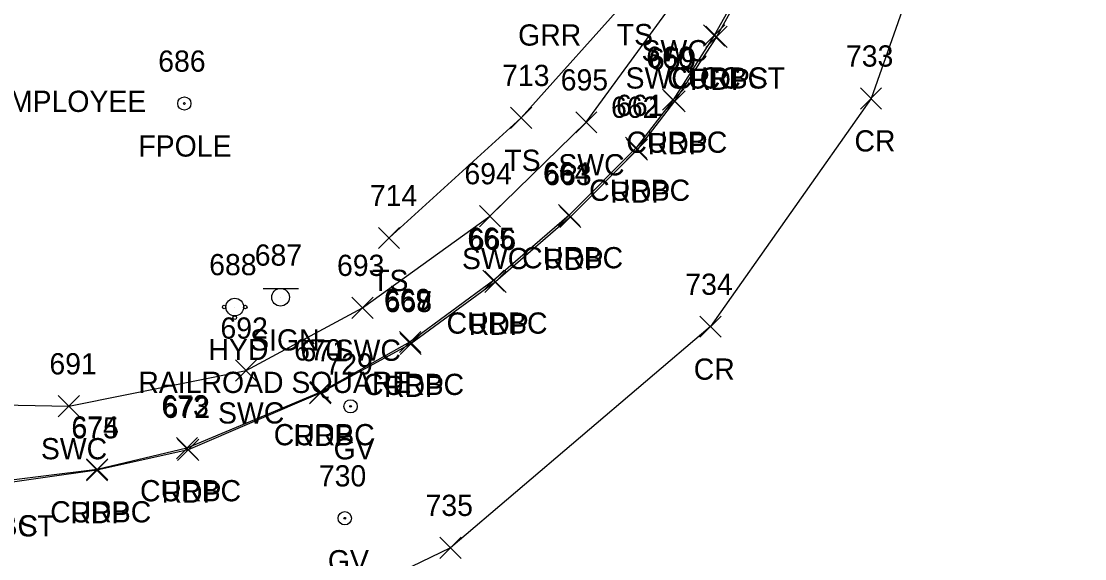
# Model space of a CAD drawing. Extents: x 1715662 to 1717487, y 887396 to 890004.
# Drawn here: x 1716519.9 to 1716620, y 888252.4 to 888303 of the extents above; entities that cross this region are included whole.
import ezdxf

# ---------------------------------------------------------------- set-up
doc = ezdxf.new("R2010")
doc.units = 0
for name, color, linetype in [('L_A', 7, 'Continuous'), ('L_I', 7, 'Continuous'), ('L_TIC', 7, 'Continuous'), ('LELB', 7, 'Continuous'), ('LFP', 7, 'Continuous'), ('P_A', 7, 'Continuous'), ('P_I', 7, 'Continuous'), ('P_TIC', 7, 'Continuous'), ('PET', 7, 'Continuous'), ('PRC', 7, 'Continuous'), ('R_A', 7, 'Continuous'), ('R_I', 7, 'Continuous'), ('R_TIC', 7, 'Continuous'), ('RC', 7, 'Continuous'), ('RSW', 7, 'Continuous'), ('S_A', 7, 'Continuous'), ('S_C', 7, 'Continuous'), ('S_I', 7, 'Continuous'), ('SSGN', 7, 'Continuous'), ('U_A', 7, 'Continuous'), ('U_I', 7, 'Continuous'), ('UWFH', 7, 'Continuous'), ('UWV', 7, 'Continuous')]:
    doc.layers.add(name, color=color, linetype=linetype)

msp = doc.modelspace()

# ---------------------------------------------------------------- linework, layer by layer
at = {"layer": 'L_TIC'}
for points in [[(1716565.96, 888292.94), (1716567.96, 888294.94)], [(1716567.96, 888292.94), (1716565.96, 888294.94)], [(1716553.51, 888281.62), (1716555.51, 888283.62)], [(1716555.51, 888281.62), (1716553.51, 888283.62)]]:
    msp.add_lwpolyline(points, dxfattribs=at)
at = {"layer": 'LELB'}
msp.add_lwpolyline([(1716582.79, 888318.54), (1716577.55, 888305.79), (1716566.96, 888293.94), (1716554.51, 888282.62)], dxfattribs=at)
at = {"layer": 'LFP'}
for radius in [0.625, 0.0833]:
    msp.add_circle((1716535.23, 888295.29), radius, dxfattribs=at)
at = {"layer": 'P_TIC'}
for points in [[(1716584.36, 888300.58), (1716586.36, 888302.58)], [(1716586.36, 888300.58), (1716584.36, 888302.58)], [(1716580.39, 888294.5), (1716582.39, 888296.5)], [(1716582.39, 888294.5), (1716580.39, 888296.5)], [(1716598.91, 888294.77), (1716600.91, 888296.77)], [(1716600.91, 888294.77), (1716598.91, 888296.77)], [(1716576.87, 888289.94), (1716578.87, 888291.94)], [(1716578.87, 888289.94), (1716576.87, 888291.94)], [(1716570.59, 888283.6), (1716572.59, 888285.6)], [(1716572.59, 888283.6), (1716570.59, 888285.6)], [(1716563.54, 888277.49), (1716565.54, 888279.49)], [(1716565.54, 888277.49), (1716563.54, 888279.49)], [(1716583.78, 888273.26), (1716585.78, 888275.26)], [(1716585.78, 888273.26), (1716583.78, 888275.26)], [(1716555.55, 888271.64), (1716557.55, 888273.64)], [(1716557.55, 888271.64), (1716555.55, 888273.64)], [(1716555.55, 888271.63), (1716557.55, 888273.63)], [(1716557.55, 888271.63), (1716555.55, 888273.63)], [(1716547.02, 888267), (1716549.02, 888269)], [(1716549.02, 888267), (1716547.02, 888269)], [(1716534.59, 888261.66), (1716536.59, 888263.66)], [(1716536.59, 888261.66), (1716534.59, 888263.66)], [(1716526, 888259.73), (1716528, 888261.73)], [(1716528, 888259.73), (1716526, 888261.73)], [(1716559.31, 888252.42), (1716561.31, 888254.42)], [(1716561.31, 888252.42), (1716559.31, 888254.42)]]:
    msp.add_lwpolyline(points, dxfattribs=at)
at = {"layer": 'PET'}
msp.add_lwpolyline([(1716628.39, 888359.45), (1716612.85, 888359.68), (1716598.29, 888359.77), (1716597.92, 888344.73), (1716597.23, 888336.42), (1716596.07, 888329.81), (1716593.67, 888319.98), (1716591.95, 888314.93), (1716590.61, 888311.07), (1716585.36, 888301.58), (1716581.39, 888295.5), (1716577.87, 888290.94), (1716571.59, 888284.6), (1716564.54, 888278.49), (1716556.55, 888272.63), (1716556.55, 888272.64), (1716548.02, 888268), (1716535.59, 888262.66), (1716527, 888260.73), (1716516.57, 888259.25)], dxfattribs=at)
at = {"layer": 'PRC'}
msp.add_lwpolyline([(1716612.85, 888359.68), (1716612.17, 888345.49), (1716610.23, 888325.05), (1716599.91, 888295.77), (1716584.78, 888274.26), (1716560.31, 888253.42), (1716535.28, 888241.32), (1716471.98, 888238.42), (1716446.91, 888240.45), (1716423.44, 888242.23), (1716395.99, 888243.46), (1716360.07, 888243.38), (1716329.01, 888242.88), (1716285.79, 888240.52), (1716253.17, 888237.3), (1716220.47, 888232.04), (1716184.13, 888222.3), (1716155.75, 888211.83), (1716125.79, 888199.82), (1716096.66, 888186.57)], dxfattribs=at)
at = {"layer": 'R_TIC'}
for points in [[(1716584.13, 888300.7), (1716586.13, 888302.7)], [(1716586.13, 888300.7), (1716584.13, 888302.7)], [(1716584.13, 888300.7), (1716586.13, 888302.7)], [(1716586.13, 888300.7), (1716584.13, 888302.7)], [(1716580.28, 888294.65), (1716582.28, 888296.65)], [(1716582.28, 888294.65), (1716580.28, 888296.65)], [(1716572.09, 888292.52), (1716574.09, 888294.52)], [(1716574.09, 888292.52), (1716572.09, 888294.52)], [(1716576.78, 888290.12), (1716578.78, 888292.12)], [(1716578.78, 888290.12), (1716576.78, 888292.12)], [(1716563.02, 888283.68), (1716565.02, 888285.68)], [(1716565.02, 888283.68), (1716563.02, 888285.68)], [(1716570.47, 888283.76), (1716572.47, 888285.76)], [(1716572.47, 888283.76), (1716570.47, 888285.76)], [(1716563.35, 888277.6), (1716565.35, 888279.6)], [(1716565.35, 888277.6), (1716563.35, 888279.6)], [(1716551.02, 888275.04), (1716553.02, 888277.04)], [(1716553.02, 888275.04), (1716551.02, 888277.04)], [(1716555.49, 888271.82), (1716557.49, 888273.82)], [(1716557.49, 888271.82), (1716555.49, 888273.82)], [(1716540.04, 888269.13), (1716542.04, 888271.13)], [(1716542.04, 888269.13), (1716540.04, 888271.13)], [(1716547.07, 888267.08), (1716549.07, 888269.08)], [(1716549.07, 888267.08), (1716547.07, 888269.08)], [(1716523.36, 888265.76), (1716525.36, 888267.76)], [(1716525.36, 888265.76), (1716523.36, 888267.76)], [(1716534.48, 888261.8), (1716536.48, 888263.8)], [(1716536.48, 888261.8), (1716534.48, 888263.8)], [(1716526.01, 888259.81), (1716528.01, 888261.81)], [(1716528.01, 888259.81), (1716526.01, 888261.81)]]:
    msp.add_lwpolyline(points, dxfattribs=at)
at = {"layer": 'RC'}
msp.add_lwpolyline([(1716585.13, 888301.7), (1716581.28, 888295.65), (1716577.78, 888291.12), (1716571.47, 888284.76), (1716564.35, 888278.6), (1716556.49, 888272.82), (1716548.07, 888268.08), (1716535.48, 888262.8), (1716527.01, 888260.81), (1716516.36, 888259.49)], dxfattribs=at)
at = {"layer": 'RSW'}
for points in [[(1716516.36, 888259.49), (1716502.56, 888259.17), (1716502.57, 888267.72), (1716516.37, 888266.92), (1716524.36, 888266.76), (1716541.04, 888270.13), (1716552.02, 888276.04), (1716564.02, 888284.68), (1716573.09, 888293.52), (1716580.93, 888304.27), (1716586.2, 888313.47), (1716587.64, 888317.29), (1716588.87, 888321), (1716591.16, 888330.65), (1716592.41, 888340.14), (1716593.07, 888350.26), (1716593.22, 888359.77)], [(1716595.7, 888329.6), (1716593.59, 888319.97), (1716591.92, 888314.96), (1716590.47, 888311.22), (1716585.13, 888301.7)]]:
    msp.add_lwpolyline(points, dxfattribs=at)
at = {"layer": 'SSGN'}
for p, q in [((1716542.65, 888277.86), (1716545.98, 888277.86)), ((1716544.29, 888277.03), (1716544.29, 888277.03))]:
    msp.add_line(p, q, dxfattribs=at)
msp.add_circle((1716544.29, 888277.03), 0.833, dxfattribs=at)
at = {"layer": 'UWFH'}
msp.add_line((1716539.98, 888276.11), (1716539.98, 888276.11), dxfattribs=at)
for centre, radius in [((1716538.98, 888276.11), 0.167), ((1716539.98, 888276.11), 0.833), ((1716540.98, 888276.11), 0.167), ((1716539.98, 888275.11), 0.167)]:
    msp.add_circle(centre, radius, dxfattribs=at)
at = {"layer": 'UWV'}
for centre, radius in [((1716550.89, 888266.75), 0.625), ((1716550.89, 888266.75), 0.0833), ((1716550.34, 888256.2), 0.625), ((1716550.34, 888256.2), 0.0833)]:
    msp.add_circle(centre, radius, dxfattribs=at)

# ---------------------------------------------------------------- texts
at = {"layer": 'L_A'}
for s, p in [('TS', (1716575.96, 888300.79)), ('FPOLE', (1716530.9, 888290.29)), ('TS', (1716565.37, 888288.94)), ('TS', (1716552.92, 888277.62))]:
    msp.add_text(s, height=2, dxfattribs=at).set_placement(p)
at = {"layer": 'L_I'}
for s, p in [('686', (1716532.77, 888298.29)), ('713', (1716565.16, 888296.94)), ('714', (1716552.71, 888285.62))]:
    msp.add_text(s, height=2, dxfattribs=at).set_placement(p)
at = {"layer": 'P_A'}
for s, p in [('RDP', (1716582.85, 888296.58)), ('RDP', (1716578.88, 888290.5)), ('CR', (1716598.35, 888290.77)), ('RDP', (1716575.36, 888285.94)), ('RDP', (1716569.07, 888279.6)), ('RDP', (1716562.02, 888273.49)), ('CR', (1716583.21, 888269.26)), ('RDP', (1716554.04, 888267.64)), ('RDP', (1716554.04, 888267.63)), ('RDP', (1716545.51, 888263)), ('RDP', (1716533.08, 888257.66)), ('RDP', (1716524.49, 888255.73))]:
    msp.add_text(s, height=2, dxfattribs=at).set_placement(p)
at = {"layer": 'P_I'}
for s, p in [('659', (1716578.98, 888298.5)), ('733', (1716597.55, 888298.77)), ('662', (1716575.42, 888293.94)), ('663', (1716569.13, 888287.6)), ('666', (1716562.02, 888281.49)), ('734', (1716582.42, 888277.26)), ('668', (1716554.1, 888275.64)), ('667', (1716554.09, 888275.63)), ('671', (1716546.18, 888271)), ('672', (1716533.18, 888265.66)), ('675', (1716524.59, 888263.73)), ('735', (1716557.95, 888256.42))]:
    msp.add_text(s, height=2, dxfattribs=at).set_placement(p)
at = {"layer": 'R_A'}
for s, p in [('GRR', (1716566.67, 888300.75)), ('SWC', (1716578.29, 888299.27)), ('SWC CC ST', (1716576.79, 888296.7)), ('CURBC', (1716580.71, 888296.7)), ('CURBC', (1716576.86, 888290.65)), ('SWC', (1716570.46, 888288.52)), ('CURBC', (1716573.36, 888286.12)), ('SWC', (1716561.38, 888279.68)), ('CURBC', (1716567.05, 888279.76)), ('CURBC', (1716559.93, 888273.6)), ('SWC', (1716549.39, 888271.04)), ('CURBC', (1716552.07, 888267.82)), ('SWC', (1716538.4, 888265.13)), ('CURBC', (1716543.65, 888263.08)), ('SWC', (1716521.72, 888261.76)), ('CURBC', (1716531.06, 888257.8)), ('CURBC', (1716522.6, 888255.81)), ('CC SWC ST', (1716508.02, 888254.49)), ('CURBC', (1716511.94, 888254.49))]:
    msp.add_text(s, height=2, dxfattribs=at).set_placement(p)
at = {"layer": 'R_I'}
for s, p in [('660', (1716578.74, 888298.65)), ('695', (1716570.68, 888296.52)), ('661', (1716575.89, 888294.12)), ('694', (1716561.61, 888287.68)), ('664', (1716569.01, 888287.76)), ('665', (1716561.89, 888281.6)), ('693', (1716549.61, 888279.04)), ('669', (1716554.03, 888275.82)), ('692', (1716538.63, 888273.13)), ('670', (1716545.57, 888271.08)), ('691', (1716522.52, 888269.76)), ('673', (1716533.07, 888265.8)), ('674', (1716524.6, 888263.81))]:
    msp.add_text(s, height=2, dxfattribs=at).set_placement(p)
at = {"layer": 'S_A'}
msp.add_text('SIGN', height=2, dxfattribs=at).set_placement((1716541.43, 888272.01))
at = {"layer": 'S_C'}
for s, p in [('GRANITE RAILROAD EMPLOYEE', (1716489.88, 888294.5)), ('RAILROAD SQUARE', (1716530.9, 888268.01))]:
    msp.add_text(s, height=2, dxfattribs=at).set_placement(p)
at = {"layer": 'S_I'}
msp.add_text('687', height=2, dxfattribs=at).set_placement((1716541.86, 888280.01))
at = {"layer": 'U_A'}
for s, p in [('HYD', (1716537.5, 888271.11)), ('GV', (1716549.29, 888261.75)), ('GV', (1716548.75, 888251.2))]:
    msp.add_text(s, height=2, dxfattribs=at).set_placement(p)
at = {"layer": 'U_I'}
for s, p in [('688', (1716537.57, 888279.11)), ('729', (1716548.52, 888269.75)), ('730', (1716547.9, 888259.2))]:
    msp.add_text(s, height=2, dxfattribs=at).set_placement(p)

doc.saveas('drawing.dxf')
